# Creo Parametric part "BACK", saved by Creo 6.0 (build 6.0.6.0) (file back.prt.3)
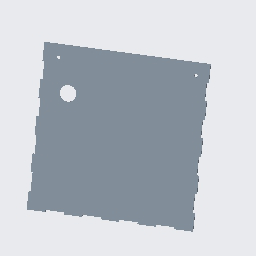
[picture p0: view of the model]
Units: Inch lbm Second (Pro/E Default); INCH, POUND, SECS

Created from: INLBS_PART_SOLID.PRT

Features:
  1. datum plane "RIGHT"
  2. datum plane "TOP"
  3. datum plane "FRONT"
  4. coordinate system
  5. sketch "Sketch 1"
  6. extrusion "Extrude 1"
  7. sketch "Sketch 3"
  8. extruded cut "Extrude 2"
  9. sketch "Sketch 4"
  10. extruded cut "Extrude 3"

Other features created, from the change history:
  sketch "Sketch 4"
  extruded cut "Extrude 3"

Surfaces: 54 plane, 3 cylinder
